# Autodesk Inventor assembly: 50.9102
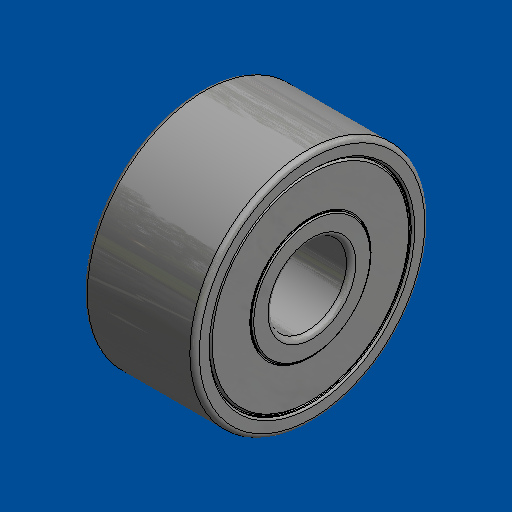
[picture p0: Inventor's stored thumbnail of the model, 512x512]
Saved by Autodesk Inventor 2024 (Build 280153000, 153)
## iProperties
Company: CADENAS
Created: 2022-08
Part Number: 50.9102
Description: STEP AP214
Document SubType Name: Assembly
Designer: amoles
Stock Number: 5200 2RS DOUBLE ROW ANGULAR CONTACT BEARING
Sending System: PARTsolutions
Preprocessor: ST-DEVELOPER v18.102
Title: 5200 2RS
Author: License CC BY-ND 4.0
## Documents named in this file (5)
- L:\INVENTOR LIBRARIES\PARTS LIBRARY\MACHINE ELEMENTS\BALL BEARINGS\50.9102 5200 2RS DOUBLE ROW ANGULAR CONTACT BEARING 10mm ID - 30MM OD.iam
- L:\INVENTOR LIBRARIES\PARTS LIBRARY\MACHINE ELEMENTS\BALL BEARINGS\SUBCOMPONENTS\50.9102 5200 2RS-Seal.ipt
- L:\INVENTOR LIBRARIES\PARTS LIBRARY\MACHINE ELEMENTS\BALL BEARINGS\SUBCOMPONENTS\50.9102 5200 2RS-Ball.ipt
- L:\INVENTOR LIBRARIES\PARTS LIBRARY\MACHINE ELEMENTS\BALL BEARINGS\SUBCOMPONENTS\50.9102 5200 2RS-Outer Ring.ipt
- L:\INVENTOR LIBRARIES\PARTS LIBRARY\MACHINE ELEMENTS\BALL BEARINGS\SUBCOMPONENTS\50.9102 5200 2RS-Inner Ring.ipt
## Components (18 placed, 18 different names)
1. NAUO1
2. NAUO2
3. NAUO3
4. NAUO4
5. NAUO5
6. NAUO6
7. NAUO7
8. NAUO8
9. NAUO9
10. NAUO10
11. NAUO11
12. NAUO12
13. NAUO13
14. NAUO14
15. NAUO15
16. NAUO16
17. NAUO17
18. NAUO18
